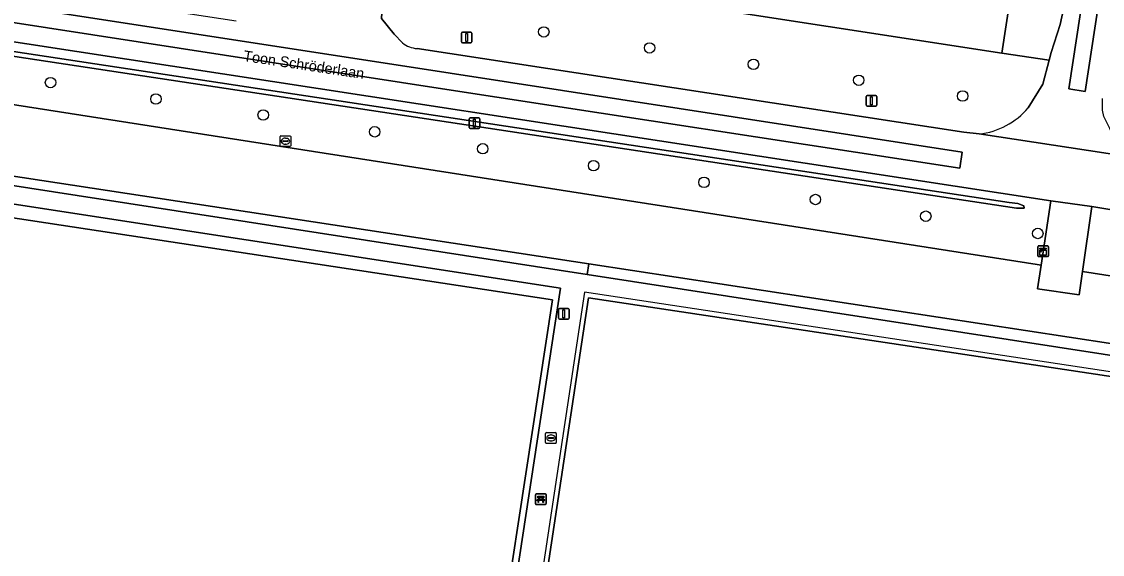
# Model space of a CAD drawing. Extents: x 161090 to 161692, y 379509 to 380907.
# Drawn here: x 161358.3 to 161459.2, y 380121.1 to 380170.9 of the extents above; entities that cross this region are included whole.
import ezdxf

# ---------------------------------------------------------------- set-up
doc = ezdxf.new("R2010")
doc.units = 0
for name, color, linetype in [('IMGEO_Afsluitpaal', 7, 'Continuous'), ('IMGEO_Bank', 7, 'Continuous'), ('IMGEO_Boom', 7, 'Continuous'), ('IMGEO_Greppel_droge_sloot', 7, 'Continuous'), ('IMGEO_Groenvoorziening', 7, 'Continuous'), ('IMGEO_Haag', 7, 'Continuous'), ('IMGEO_Hek', 7, 'Continuous'), ('IMGEO_Kast', 7, 'Continuous'), ('IMGEO_Kolk', 7, 'Continuous'), ('IMGEO_Lichtmast', 7, 'Continuous'), ('IMGEO_Openbare_ruimte_label', 7, 'Continuous'), ('IMGEO_Rijbaan_lokaal_gesloten', 7, 'Continuous'), ('IMGEO_Rijbaan_lokaal_open', 7, 'Continuous'), ('IMGEO_Rioolput', 7, 'Continuous'), ('IMGEO_Terreindeel_open', 7, 'Continuous'), ('IMGEO_Voetpad_open', 7, 'Continuous')]:
    doc.layers.add(name, color=color, linetype=linetype)

msp = doc.modelspace()

# ---------------------------------------------------------------- linework, layer by layer
at = {"layer": 'IMGEO_Afsluitpaal'}
for p, q in [((161400.06, 380161), (161400.06, 380161.8)), ((161400.06, 380161.8), (161400.06, 380161)), ((161400.16, 380161.9), (161400.95, 380161.9)), ((161400.95, 380161.9), (161400.16, 380161.9)), ((161401.05, 380161.8), (161401.05, 380161)), ((161401.05, 380161), (161401.05, 380161.8)), ((161400.95, 380160.9), (161400.16, 380160.9)), ((161400.16, 380160.9), (161400.95, 380160.9))]:
    msp.add_line(p, q, dxfattribs=at)
msp.add_lwpolyline([(161400.48, 380161.77), (161400.63, 380161.77), (161400.63, 380161.02), (161400.48, 380161.02), (161400.48, 380161.77)], dxfattribs=at)
for centre, start, end in [((161400.16, 380161.8), 90, 180), ((161400.16, 380161.8), 90, 180), ((161400.95, 380161.8), 0, 90), ((161400.95, 380161.8), 360, 90), ((161400.16, 380161), 180, 270), ((161400.16, 380161), 180, 270), ((161400.95, 380161), 270, 0), ((161400.95, 380161), 270, 0)]:
    msp.add_arc(centre, 0.1, start, end, dxfattribs=at)
at = {"layer": 'IMGEO_Bank'}
for p, q in [((161406.25, 380125.87), (161406.25, 380126.71)), ((161406.25, 380126.71), (161406.25, 380125.87)), ((161406.32, 380126.79), (161407.17, 380126.79)), ((161407.17, 380126.79), (161406.32, 380126.79)), ((161406.95, 380126.19), (161406.55, 380126.19)), ((161406.56, 380126.3), (161406.56, 380126.41)), ((161406.6, 380126.41), (161406.6, 380126.3)), ((161406.89, 380126.41), (161406.61, 380126.41)), ((161406.61, 380126.29), (161406.89, 380126.29)), ((161406.9, 380126.3), (161406.9, 380126.41)), ((161406.94, 380126.41), (161406.94, 380126.3)), ((161407.25, 380126.72), (161407.25, 380125.88)), ((161407.25, 380125.88), (161407.25, 380126.72)), ((161407.18, 380125.79), (161406.33, 380125.79)), ((161406.33, 380125.79), (161407.18, 380125.79))]:
    msp.add_line(p, q, dxfattribs=at)
for points in [[(161406.5, 380126.19), (161406.35, 380126.19), (161406.47, 380126.29), (161406.55, 380126.29)], [(161406.55, 380126.41), (161406.47, 380126.41), (161406.47, 380126.57), (161407.03, 380126.57), (161407.03, 380126.41), (161406.95, 380126.41)], [(161406.55, 380126.19), (161406.55, 380125.98), (161406.5, 380125.98), (161406.5, 380126.19)], [(161406.95, 380126.29), (161407.03, 380126.29), (161407.14, 380126.19), (161407, 380126.19)], [(161407, 380126.19), (161407, 380125.98), (161406.95, 380125.98), (161406.95, 380126.19)]]:
    msp.add_lwpolyline(points, dxfattribs=at)
for centre, radius, start, end in [((161406.33, 380126.72), 0.0779, 92.4484, 184.2845), ((161406.33, 380126.72), 0.0779, 92.4484, 184.2845), ((161406.5, 380126.18), 0.00671, 2.8957, 87.1043), ((161406.55, 380126.41), 0.00671, 2.8957, 87.1043), ((161406.55, 380126.3), 0.00671, 272.8957, 357.1043), ((161406.55, 380126.18), 0.00671, 92.8957, 177.1043), ((161406.61, 380126.41), 0.00671, 92.8957, 177.1043), ((161406.61, 380126.3), 0.00671, 182.8957, 267.1043), ((161406.89, 380126.41), 0.00671, 2.8957, 87.1043), ((161406.89, 380126.3), 0.00671, 272.8957, 357.1043), ((161406.95, 380126.41), 0.00671, 92.8957, 177.1043), ((161406.95, 380126.3), 0.00671, 182.8957, 267.1043), ((161406.95, 380126.18), 0.00671, 2.8957, 87.1043), ((161407, 380126.18), 0.00671, 92.8957, 177.1043), ((161407.17, 380126.72), 0.0779, 2.4484, 94.2845), ((161407.17, 380126.72), 0.0779, 2.4484, 94.2845), ((161406.33, 380125.87), 0.0779, 182.4484, 274.2845), ((161406.33, 380125.87), 0.0779, 182.4484, 274.2845), ((161407.17, 380125.87), 0.0779, 272.4484, 4.2845), ((161407.17, 380125.87), 0.0779, 272.4484, 4.2845)]:
    msp.add_arc(centre, radius, start, end, dxfattribs=at)
at = {"layer": 'IMGEO_Boom'}
for centre in [(161407.03, 380169.91), (161416.91, 380168.42), (161426.61, 380166.89), (161360.97, 380165.18), (161436.44, 380165.4), (161446.14, 380163.93), (161370.81, 380163.65), (161380.83, 380162.16), (161391.24, 380160.59), (161401.33, 380159.01), (161411.68, 380157.43), (161421.99, 380155.87), (161432.39, 380154.27), (161442.7, 380152.71), (161453.16, 380151.1)]:
    msp.add_circle(centre, 0.489, dxfattribs=at)
at = {"layer": 'IMGEO_Greppel_droge_sloot'}
msp.add_lwpolyline([(161347.75, 380169.11), (161451.18, 380153.45), (161451.9, 380153.46), (161451.85, 380153.69), (161451.3, 380153.9), (161450.48, 380153.99), (161348.46, 380169.46), (161347.39, 380169.53), (161347.35, 380169.4), (161347.45, 380169.3)], close=True, dxfattribs=at)
at = {"layer": 'IMGEO_Groenvoorziening'}
for points in [[(161462.38, 380216.19), (161462.36, 380216.53), (161461.82, 380217.55), (161461.58, 380217.85), (161457.51, 380218.39), (161453.4, 380191.53), (161449.79, 380167.94), (161454.23, 380167.29), (161454.42, 380167.98), (161455.26, 380170.61), (161455.87, 380173.51), (161457.01, 380179.89), (161457.86, 380185.83)], [(161448.97, 380187.6), (161446.95, 380185.82), (161437.98, 380182.07), (161427.8, 380177.94), (161420.92, 380175.96), (161419.04, 380174.65), (161417.36, 380172.94), (161449.79, 380167.94), (161453.4, 380191.53), (161452.93, 380191.12)], [(161345.12, 380170.87), (161344.11, 380164.89), (161349.66, 380163.79), (161350.17, 380163.69), (161351.24, 380163.47), (161351.41, 380164.08), (161453.11, 380148.2), (161453.47, 380148.15), (161454.38, 380154.14)], [(161347.75, 380169.11), (161347.45, 380169.3), (161347.35, 380169.4), (161347.39, 380169.53), (161348.46, 380169.46), (161450.48, 380153.99), (161451.3, 380153.9), (161451.85, 380153.69), (161451.9, 380153.46), (161451.18, 380153.45)], [(161351.41, 380164.08), (161351.24, 380163.47), (161350.31, 380157.54), (161411.22, 380148.26), (161468.31, 380139.56), (161469.3, 380145.67), (161457.33, 380147.54), (161457.02, 380145.37), (161453.13, 380145.92), (161453.47, 380148.15), (161453.11, 380148.2)], [(161411.07, 380147.27), (161411.22, 380148.26), (161350.31, 380157.54), (161350.18, 380156.7), (161408.47, 380147.67)], [(161470.25, 380151.63), (161458.19, 380153.61), (161457.33, 380147.54), (161469.3, 380145.67)], [(161411.22, 380148.26), (161411.07, 380147.27), (161468.14, 380138.48), (161468.3, 380139.49), (161468.31, 380139.56)]]:
    msp.add_lwpolyline(points, close=True, dxfattribs=at)
for points in [[(161417.36, 380172.94), (161392.61, 380176.75), (161391.93, 380172.2), (161391.86, 380171.16), (161393.06, 380169.69), (161393.83, 380168.89)], [(161452.27, 380162.84), (161453.62, 380165.04), (161454.23, 380167.29), (161449.79, 380167.94), (161417.36, 380172.94)], [(161395.21, 380168.35), (161446.26, 380160.56), (161447.68, 380160.39)]]:
    msp.add_lwpolyline(points, dxfattribs=at)
for centre, radius, start, end in [((161395.46, 380171.04), 2.7, 232.8095, 264.5934), ((161446.94, 380167.3), 6.95, 276.0949, 320.0798)]:
    msp.add_arc(centre, radius, start, end, dxfattribs=at)
at = {"layer": 'IMGEO_Haag'}
for points in [[(161411.07, 380147.27), (161411.22, 380148.26), (161350.31, 380157.54), (161350.18, 380156.7), (161408.47, 380147.67)], [(161411.22, 380148.26), (161411.07, 380147.27), (161468.14, 380138.48), (161468.3, 380139.49), (161468.31, 380139.56)]]:
    msp.add_lwpolyline(points, close=True, dxfattribs=at)
at = {"layer": 'IMGEO_Hek'}
for points in [[(161453.4, 380191.53), (161449.79, 380167.94)], [(161449.79, 380167.94), (161417.36, 380172.94)], [(161335.68, 380060.71), (161349.84, 380155.01), (161408.6, 380146), (161401.57, 380099.88), (161400.07, 380089.73)], [(161395.98, 380047.27), (161454.44, 380038.44), (161461.18, 380082.48), (161462.71, 380082.27), (161463.97, 380090.7), (161464.23, 380092.46), (161462.73, 380092.72), (161469.38, 380136.76), (161410.83, 380145.62), (161395.98, 380047.27)]]:
    msp.add_lwpolyline(points, dxfattribs=at)
at = {"layer": 'IMGEO_Kast'}
for p, q in [((161453.16, 380149.01), (161453.16, 380149.85)), ((161453.16, 380149.85), (161453.16, 380149.01)), ((161453.23, 380149.94), (161454.07, 380149.94)), ((161454.07, 380149.94), (161453.23, 380149.94)), ((161454.16, 380149.86), (161454.16, 380149.02)), ((161454.16, 380149.02), (161454.16, 380149.86)), ((161454.08, 380148.94), (161453.24, 380148.94)), ((161453.24, 380148.94), (161454.08, 380148.94))]:
    msp.add_line(p, q, dxfattribs=at)
for points in [[(161453.35, 380149.73), (161453.95, 380149.73), (161453.95, 380149.64), (161453.35, 380149.64), (161453.35, 380149.73)], [(161453.35, 380149.55), (161453.95, 380149.55), (161453.95, 380149.06), (161453.35, 380149.06), (161453.35, 380149.55)]]:
    msp.add_lwpolyline(points, dxfattribs=at)
msp.add_circle((161453.44, 380149.4), 0.0377, dxfattribs=at)
for centre, start, end in [((161453.24, 380149.86), 92.4484, 184.2845), ((161453.24, 380149.86), 92.4484, 184.2845), ((161454.08, 380149.86), 2.4484, 94.2845), ((161454.08, 380149.86), 2.4484, 94.2845), ((161453.24, 380149.01), 182.4484, 274.2845), ((161453.24, 380149.01), 182.4484, 274.2845), ((161454.08, 380149.01), 272.4484, 4.2845), ((161454.08, 380149.01), 272.4484, 4.2845)]:
    msp.add_arc(centre, 0.0779, start, end, dxfattribs=at)
at = {"layer": 'IMGEO_Kolk'}
for p, q in [((161407.2, 380131.59), (161407.2, 380132.44)), ((161407.27, 380132.52), (161408.13, 380132.52)), ((161407.69, 380132.29), (161407.71, 380132.29)), ((161408.2, 380132.44), (161408.2, 380131.59)), ((161408.13, 380131.51), (161407.27, 380131.51)), ((161407.46, 380132.01), (161407.46, 380132.02)), ((161407.5, 380132.06), (161407.9, 380132.06)), ((161407.9, 380131.97), (161407.5, 380131.97)), ((161407.71, 380131.74), (161407.68, 380131.74)), ((161407.94, 380132.02), (161407.94, 380132.01))]:
    msp.add_line(p, q, dxfattribs=at)
for points in [[(161407.2, 380131.59), (161407.2, 380132.44)], [(161407.27, 380132.52), (161408.13, 380132.52)], [(161408.2, 380132.44), (161408.2, 380131.59)], [(161408.13, 380131.51), (161407.27, 380131.51)]]:
    msp.add_lwpolyline(points, dxfattribs=at)
for centre, radius, start, end in [((161407.28, 380132.44), 0.0765, 91.552, 178.448), ((161407.28, 380132.44), 0.0765, 91.552, 178.448), ((161408.12, 380132.44), 0.0765, 1.552, 88.448), ((161408.12, 380132.44), 0.0765, 1.552, 88.448), ((161407.28, 380131.59), 0.0765, 181.552, 268.448), ((161407.28, 380131.59), 0.0765, 181.552, 268.448), ((161407.5, 380132.02), 0.0403, 85.8775, 175.7526), ((161407.49, 380132.01), 0.0366, 178.938, 274.7102), ((161407.9, 380132.02), 0.0386, 1.7309, 96.639), ((161407.9, 380132.01), 0.043, 264.8664, 352.4533), ((161408.12, 380131.59), 0.0765, 271.552, 358.448), ((161408.12, 380131.59), 0.0765, 271.552, 358.448)]:
    msp.add_arc(centre, radius, start, end, dxfattribs=at)
for centre, major_axis, ratio, start_param, end_param in [((161407.69, 380132.01), (-0.387, 0.002), 0.722429, 4.712389, 7.853982), ((161407.71, 380132.01), (-0.39, 0.002), 0.717154, 1.570796, 4.712389)]:
    msp.add_ellipse(centre, major_axis=major_axis, ratio=ratio, start_param=start_param, end_param=end_param, dxfattribs=at)
at = {"layer": 'IMGEO_Lichtmast'}
for p, q in [((161399.33, 380169), (161399.33, 380169.8)), ((161399.33, 380169.8), (161399.33, 380169)), ((161399.43, 380169.9), (161400.22, 380169.9)), ((161400.22, 380169.9), (161399.43, 380169.9)), ((161400.32, 380169.8), (161400.32, 380169)), ((161400.32, 380169), (161400.32, 380169.8)), ((161400.22, 380168.9), (161399.43, 380168.9)), ((161399.43, 380168.9), (161400.22, 380168.9)), ((161437.13, 380163.08), (161437.13, 380163.88)), ((161437.13, 380163.88), (161437.13, 380163.08)), ((161437.23, 380163.98), (161438.02, 380163.98)), ((161438.02, 380163.98), (161437.23, 380163.98)), ((161438.12, 380163.88), (161438.12, 380163.08)), ((161438.12, 380163.08), (161438.12, 380163.88)), ((161438.02, 380162.98), (161437.23, 380162.98)), ((161437.23, 380162.98), (161438.02, 380162.98)), ((161408.4, 380143.2), (161408.4, 380144)), ((161408.4, 380144), (161408.4, 380143.2)), ((161408.5, 380144.1), (161409.29, 380144.1)), ((161409.29, 380144.1), (161408.5, 380144.1)), ((161409.39, 380144), (161409.39, 380143.2)), ((161409.39, 380143.2), (161409.39, 380144)), ((161409.29, 380143.1), (161408.5, 380143.1)), ((161408.5, 380143.1), (161409.29, 380143.1))]:
    msp.add_line(p, q, dxfattribs=at)
for points in [[(161399.75, 380169.78), (161399.9, 380169.78), (161399.9, 380169.03), (161399.75, 380169.03), (161399.75, 380169.78)], [(161437.55, 380163.85), (161437.7, 380163.85), (161437.7, 380163.1), (161437.55, 380163.1), (161437.55, 380163.85)], [(161408.82, 380143.98), (161408.97, 380143.98), (161408.97, 380143.23), (161408.82, 380143.23), (161408.82, 380143.98)]]:
    msp.add_lwpolyline(points, dxfattribs=at)
for centre, start, end in [((161399.43, 380169.8), 90, 180), ((161399.43, 380169.8), 90, 180), ((161400.22, 380169.8), 0, 90), ((161400.22, 380169.8), 360, 90), ((161399.43, 380169), 180, 270), ((161399.43, 380169), 180, 270), ((161400.22, 380169), 270, 0), ((161400.22, 380169), 270, 0), ((161437.23, 380163.88), 90, 180), ((161437.23, 380163.88), 90, 180), ((161438.02, 380163.88), 0, 90), ((161438.02, 380163.88), 360, 90), ((161437.23, 380163.08), 180, 270), ((161437.23, 380163.08), 180, 270), ((161438.02, 380163.08), 270, 0), ((161438.02, 380163.08), 270, 0), ((161408.5, 380144), 90, 180), ((161408.5, 380144), 90, 180), ((161408.5, 380143.2), 180, 270), ((161408.5, 380143.2), 180, 270), ((161409.29, 380144), 0, 90), ((161409.29, 380144), 360, 90), ((161409.29, 380143.2), 270, 0), ((161409.29, 380143.2), 270, 0)]:
    msp.add_arc(centre, 0.1, start, end, dxfattribs=at)
at = {"layer": 'IMGEO_Rijbaan_lokaal_gesloten'}
for points in [[(161467.6, 380229.99), (161457.57, 380164.36), (161456.07, 380164.6), (161466.09, 380230.2)], [(161462.38, 380216.19), (161457.86, 380185.83), (161457.01, 380179.89), (161455.87, 380173.51), (161455.26, 380170.61), (161454.42, 380167.98), (161454.23, 380167.29), (161453.62, 380165.04), (161452.27, 380162.84)], [(161378.31, 380170.92), (161341.27, 380176.58), (161339.41, 380176.86), (161339.23, 380176.89), (161325.57, 380179.06), (161324.07, 380179.54), (161320.89, 380174.79), (161323.14, 380174.39), (161329.94, 380173.17), (161337.29, 380172.06), (161342.45, 380171.27), (161343.32, 380171.14), (161345.12, 380170.87), (161454.38, 380154.14), (161458.19, 380153.61), (161470.25, 380151.63)], [(161393.83, 380168.89), (161393.06, 380169.69), (161391.86, 380171.16), (161391.93, 380172.2), (161392.61, 380176.75), (161384.85, 380177.94), (161384.19, 380173.07)], [(161462.99, 380158.07), (161447.68, 380160.39), (161446.26, 380160.56), (161395.21, 380168.35)], [(161447.68, 380160.39), (161462.99, 380158.07), (161461.8, 380158.57), (161460.87, 380159.19), (161460.32, 380159.94), (161459.87, 380160.9), (161459.34, 380162.03), (161459.19, 380162.61), (161459.2, 380163.7)]]:
    msp.add_lwpolyline(points, dxfattribs=at)
msp.add_lwpolyline([(161446.09, 380158.69), (161445.88, 380157.19), (161397.98, 380164.53), (161323.36, 380176.07), (161323.62, 380177.58), (161398.28, 380166.05)], close=True, dxfattribs=at)
for centre, radius, start, end in [((161395.46, 380171.04), 2.7, 232.8095, 264.5934), ((161446.94, 380167.3), 6.95, 276.0949, 320.0798)]:
    msp.add_arc(centre, radius, start, end, dxfattribs=at)
at = {"layer": 'IMGEO_Rijbaan_lokaal_open'}
for points in [[(161496.97, 380422.69), (161497.3, 380424.9), (161498.54, 380426.72), (161500.8, 380441.25), (161501.47, 380445.59), (161499.02, 380445.99), (161498.37, 380441.76), (161495.52, 380423.04), (161485.86, 380359.57), (161485.81, 380359.38), (161483.98, 380347.23), (161466.09, 380230.2), (161456.07, 380164.6), (161457.57, 380164.36), (161467.6, 380229.99), (161485.51, 380347.04), (161487.31, 380359.08), (161487.33, 380359.34)], [(161323.62, 380177.58), (161323.36, 380176.07), (161397.98, 380164.53), (161445.88, 380157.19), (161446.09, 380158.69), (161398.28, 380166.05)]]:
    msp.add_lwpolyline(points, close=True, dxfattribs=at)
at = {"layer": 'IMGEO_Rioolput'}
for p, q in [((161382.4, 380159.29), (161382.4, 380160.14)), ((161382.48, 380160.21), (161383.33, 380160.21)), ((161382.66, 380159.71), (161382.66, 380159.72)), ((161382.7, 380159.76), (161383.1, 380159.76)), ((161383.1, 380159.67), (161382.7, 380159.67)), ((161382.89, 380159.99), (161382.91, 380159.99)), ((161382.91, 380159.43), (161382.89, 380159.43)), ((161383.14, 380159.72), (161383.14, 380159.71)), ((161383.4, 380160.14), (161383.4, 380159.29)), ((161383.33, 380159.21), (161382.48, 380159.21))]:
    msp.add_line(p, q, dxfattribs=at)
for points in [[(161382.4, 380159.29), (161382.4, 380160.14)], [(161382.48, 380160.21), (161383.33, 380160.21)], [(161383.4, 380160.14), (161383.4, 380159.29)], [(161383.33, 380159.21), (161382.48, 380159.21)]]:
    msp.add_lwpolyline(points, dxfattribs=at)
for centre, radius, start, end in [((161382.48, 380160.14), 0.0765, 91.552, 178.448), ((161382.48, 380160.14), 0.0765, 91.552, 178.448), ((161382.7, 380159.72), 0.0403, 85.8775, 175.7526), ((161382.7, 380159.71), 0.0366, 178.938, 274.7102), ((161383.11, 380159.72), 0.0386, 1.7309, 96.639), ((161383.1, 380159.71), 0.043, 264.8664, 352.4533), ((161383.33, 380160.14), 0.0765, 1.552, 88.448), ((161383.33, 380160.14), 0.0765, 1.552, 88.448), ((161382.48, 380159.29), 0.0765, 181.552, 268.448), ((161382.48, 380159.29), 0.0765, 181.552, 268.448), ((161383.33, 380159.29), 0.0765, 271.552, 358.448), ((161383.33, 380159.29), 0.0765, 271.552, 358.448)]:
    msp.add_arc(centre, radius, start, end, dxfattribs=at)
for centre, major_axis, ratio, start_param, end_param in [((161382.89, 380159.71), (-0.387, 0.002), 0.722429, 4.712389, 7.853982), ((161382.91, 380159.71), (-0.39, 0.002), 0.717154, 1.570796, 4.712389)]:
    msp.add_ellipse(centre, major_axis=major_axis, ratio=ratio, start_param=start_param, end_param=end_param, dxfattribs=at)
at = {"layer": 'IMGEO_Terreindeel_open'}
for points in [[(161407.84, 380144.89), (161350.25, 380153.65), (161342.16, 380099.98), (161335.82, 380057.58), (161393.41, 380048.84), (161400.95, 380100.03)], [(161396.47, 380047.64), (161454.09, 380038.96), (161468.87, 380136.41), (161411.19, 380145.09)]]:
    msp.add_lwpolyline(points, close=True, dxfattribs=at)
at = {"layer": 'IMGEO_Voetpad_open'}
msp.add_lwpolyline([(161467.31, 380116.65), (161470.56, 380138.12), (161469.64, 380138.25), (161468.14, 380138.48), (161411.07, 380147.27), (161408.47, 380147.67), (161350.18, 380156.7), (161349.11, 380156.86), (161348.65, 380153.9), (161340.64, 380100.12)], dxfattribs=at)
for points in [[(161393.85, 380047.41), (161399.72, 380087.36), (161400.07, 380089.73), (161401.57, 380099.88), (161408.6, 380146), (161349.84, 380155.01), (161335.68, 380060.71), (161335.04, 380056.37), (161370.36, 380050.99)], [(161393.85, 380047.41), (161370.36, 380050.99), (161335.04, 380056.37), (161335.68, 380060.71), (161349.84, 380155.01), (161408.6, 380146), (161401.57, 380099.88), (161400.07, 380089.73), (161401.03, 380089.59), (161400.68, 380087.21), (161399.72, 380087.36)], [(161393.41, 380048.84), (161335.82, 380057.58), (161342.16, 380099.98), (161350.25, 380153.65), (161407.84, 380144.89), (161400.95, 380100.03)], [(161458.19, 380153.61), (161454.38, 380154.14), (161453.47, 380148.15), (161453.13, 380145.92), (161457.02, 380145.37), (161457.33, 380147.54)], [(161411.19, 380145.09), (161468.87, 380136.41), (161454.09, 380038.96), (161396.47, 380047.64)]]:
    msp.add_lwpolyline(points, close=True, dxfattribs=at)

# ---------------------------------------------------------------- texts
at = {"layer": 'IMGEO_Openbare_ruimte_label'}
msp.add_text('Toon Schröderlaan', height=1, rotation=351.4324, dxfattribs=at).set_placement((161378.93, 380167.21))

doc.saveas('drawing.dxf')
